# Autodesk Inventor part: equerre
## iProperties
Shininess: 21.0
Length Units: 11269
Angle Units: 11279
Time Units: 11290
Mass Units: 11283
Length Display Precision: 3
Angle Display Precision: 2
Compacted: True
Created: 2001-12
Part Number: equerre
Material: Par défaut
Document SubType Name: Tôlerie
Designer: pichon
Density: 0.0
Volumn: 0.0
Area: 0.0
PropertySet Name: Model Information
Control State: 0
Master: False
Checked Out: False
Author: pichon
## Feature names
1. Extrusion1
2. Coque3
3. Congé5 [Fillet]
4. Congé4 [Fillet]
5. Extrusion2
6. Extrusion3
7. Extrusion4
8. Symétrie1 [Mirror]
9. Extrusion5
10. Chanfrein1 [Chamfer]
11. Symétrie2 [Mirror]
12. Chanfrein2 [Chamfer]
13. Chanfrein3 [Chamfer]
14. Chanfrein4 [Chamfer]
